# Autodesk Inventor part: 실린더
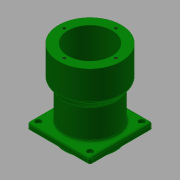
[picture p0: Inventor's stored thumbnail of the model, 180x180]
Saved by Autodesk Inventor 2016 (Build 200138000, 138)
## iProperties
Created: 2016-11
Part Number: 실린더
Material: 알루미늄 6061
Document SubType Name: Modeling
Designer: mduedu
Density: 2.71 g/cm^3
Mass: 592.083 g
Surface Area: 591.531 cm^2
Volume: 218.481 cm^3
Appearance: 진녹색
Author: mduedu
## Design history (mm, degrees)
sketch "스케치1"
  geometry: L1 (0, 0)-(0, 110); L2 (30, 0)-(30, 110); L3 (30, 110)-(42.5, 110); L4 (42.5, 110)-(42.5, 70); L5 (42.5, 70)-(35, 60); L6 (35, 60)-(35, 0); L7 (35, 0)-(30, 0)
  constraints: 14 end point, 4 parallel, 2 horizontal alignment, 1 perpendicular, 1 vertical
  dimensions: "d0" = 110 distance of L1.start L1.end; "d1" = 60 diameter of L2.end L1; "d2" = 85 diameter of L3.end L1; "d3" = 70 diameter of L6.end L1; "d4" = 40 distance of L3.end L4.end; "d5" = 50 vertical distance of L5.end L3.end
revolve "회전1" sketch "스케치1" stored, may be unused: angle "d6" = 90 deg
node "작업 평면1"
sketch "스케치2"
  geometry: L1 (-42.5, -42.5)-(42.5, -42.5); L2 (42.5, -42.5)-(42.5, 42.5); L3 (42.5, 42.5)-(-42.5, 42.5); L4 (-42.5, 42.5)-(-42.5, -42.5); L5 (-42.5, -42.5)-(42.5, 42.5); L6 (42.5, -42.5)-(-42.5, 42.5); C1 r 35 at (0, 0) reference; C2 r 35 at (0, 0); 1 further point
  constraints: 12 end point, 2 midpoint, 2 parallel, 2 perpendicular, 1 centre point, 1 coincident, 1 concentric, 1 horizontal
  dimensions: "d8" = 85 distance of L2.end L3.end
extrude "돌출1" join sketch "스케치2" distance "d10" = 8; taper "d11" = 0 deg
fillet "모깎기1" dims "d12" = 3
fillet "모깎기2" dims "d13" = 3
chamfer "모따기1" distance "d14" = 1; stored, may be unused: second distance "d15" = 2, angle "d16" = 45 deg
chamfer "모따기2" distance "d17" = 5; stored, may be unused: second distance "d18" = 2, angle "d19" = 15 deg
sketch "스케치3"
  geometry: L1 (-35, -35)-(35, -35); L2 (35, -35)-(35, 35); L3 (35, 35)-(-35, 35); L4 (-35, 35)-(-35, -35); L5 (-35, -35)-(35, 35); L6 (35, -35)-(-35, 35); 5 further points
  constraints: 12 end point, 4 coincident, 2 midpoint, 2 parallel, 1 horizontal, 1 perpendicular
  dimensions: "d20" = 70 distance of L3.end L2.end; "d21" = 70 distance of L2.end L1.end
sketch "스케치4"
  geometry: 4 further points
  constraints: 4 other
hole "구멍1" sketch "스케치4" at (-35, 35), (35, 35), (35, -35), (-35, -35) diameter "d22" = 4.5; stored, may be unused: countersink angle "d26" = 90 deg, drill point angle "d28" = 0 deg; dims "d23" = 6, "d24" = 8, "d25" = 4.6, "d27" = 8
sketch "스케치5"
  geometry: 4 further points
  constraints: 4 other
hole "구멍2" sketch "스케치5" at (0, -35), (35, 0), (-35, 0), (0, 35) diameter "d29" = 4.134; stored, may be unused: countersink angle "d33" = 90 deg, drill point angle "d35" = 120 deg; dims "d30" = 7.5, "d31" = 4, "d32" = 2, "d34" = 10
node "솔리드1"
